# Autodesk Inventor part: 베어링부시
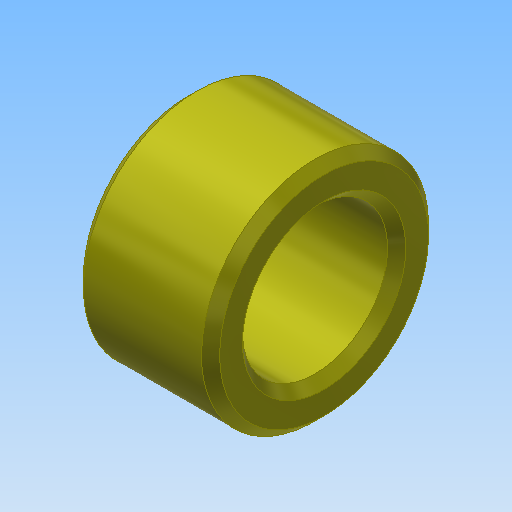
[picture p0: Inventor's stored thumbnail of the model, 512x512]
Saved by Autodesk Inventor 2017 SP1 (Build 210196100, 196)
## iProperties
Created: 2019-03
Part Number: 베어링부시
Material: 강철, 연강
Document SubType Name: Modeling
Designer: mduedu
Density: 1 g/cm^3
Appearance: 노란색
Author: mduedu
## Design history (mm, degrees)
sketch "스케치1"
  geometry: L1 (-7.5, 12.5)-(7.5, 12.5); L2 (7.5, 12.5)-(7.5, 8); L3 (7.5, 8)-(-7.5, 8); L4 (-7.5, 8)-(-7.5, 12.5); L5 (-7.5, 0)-(7.5, 0); 3 further points
  constraints: 10 end point, 2 midpoint, 2 parallel, 2 perpendicular, 2 vertical alignment, 1 coincident, 1 horizontal
  dimensions: "d0" = 16 diameter of L3 L5; "d2" = 25 diameter of L1 L5; "d3" = 15 distance of L1.start L1.end
revolve "회전1" sketch "스케치1" stored, may be unused: angle "d4" = 90 deg
chamfer "모따기1" distance "d5" = 1; stored, may be unused: second distance "d6" = 2, angle "d7" = 45 deg
chamfer "모따기2" distance "d8" = 1; stored, may be unused: second distance "d9" = 2, angle "d10" = 45 deg
node "솔리드1"
